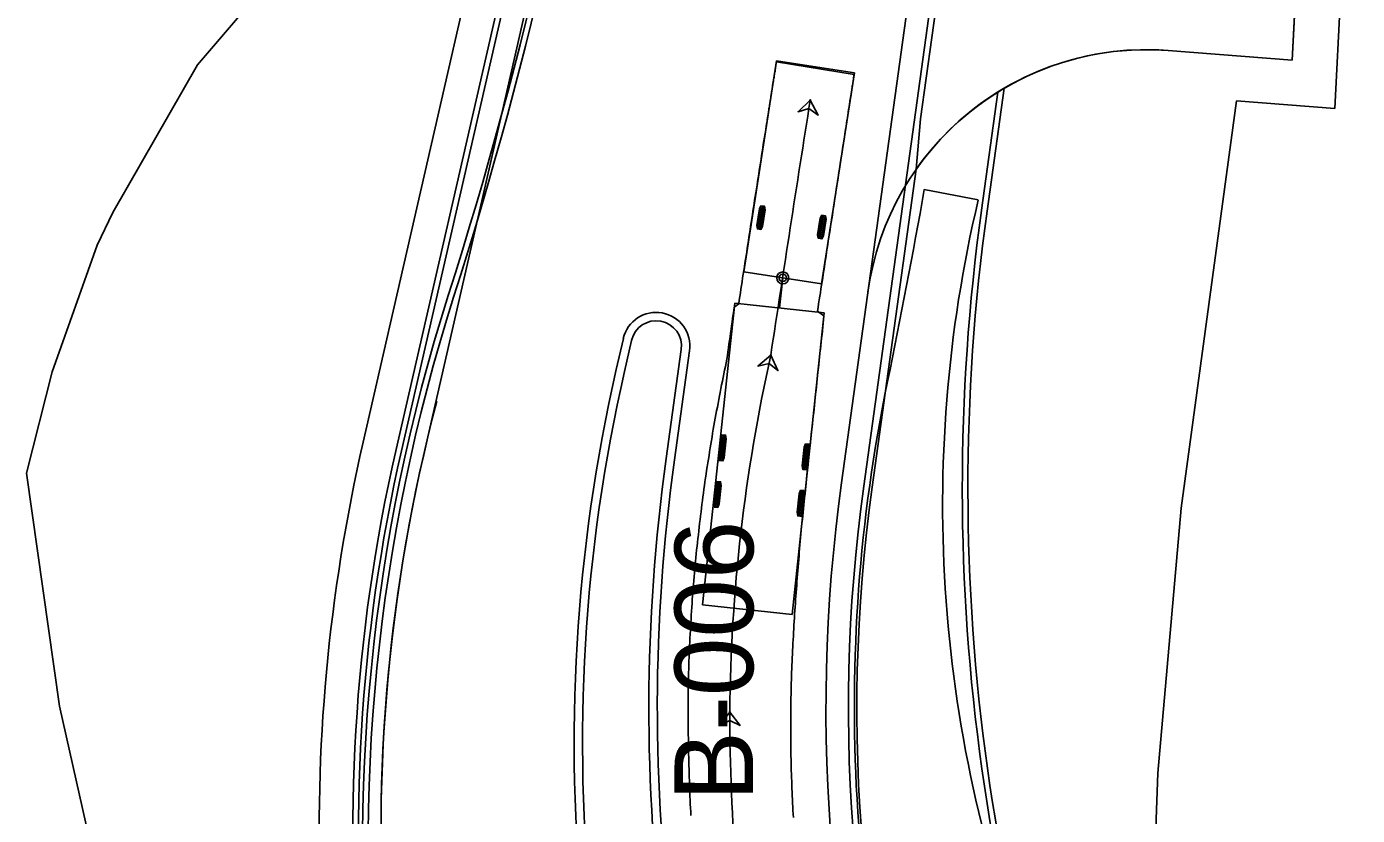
# Model space of a CAD drawing. Extents: x -14 to 1565148, y -25 to 642856.
# Drawn here: x 1564698.7 to 1564817, y 636638 to 636708.2 of the extents above; entities that cross this region are included whole.
import ezdxf

# ---------------------------------------------------------------- set-up
doc = ezdxf.new("R2010")
doc.units = 0
for name, color, linetype in [('DR_P_Drainage_Area', 7, 'Continuous'), ('DR_P_Erosion_Control', 7, 'Continuous'), ('DR_P_Headwall', 7, 'Continuous'), ('GE_X_Alignment', 7, 'Continuous'), ('PV_P_Drive', 7, 'Continuous'), ('PV_P_EOP', 7, 'Continuous'), ('PV_X_COP', 7, 'Continuous'), ('PV_X_EOP', 7, 'Continuous'), ('SC_Scratch10', 7, 'Continuous'), ('SC_Scratch2', 7, 'Continuous'), ('VG_P_Text', 7, 'Continuous')]:
    doc.layers.add(name, color=color, linetype=linetype)

msp = doc.modelspace()

# ---------------------------------------------------------------- linework, layer by layer
at = {"layer": 'DR_P_Drainage_Area'}
for centre, radius, start, end in [((1564357.36, 636804.71), 397.5, 342.3578, 1.7978), ((1564357.36, 636804.71), 398, 342.3578, 1.7978), ((1564891.02, 636634.99), 162.5, 162.3578, 209.8794), ((1564891.02, 636634.99), 162, 162.3578, 209.8794)]:
    msp.add_arc(centre, radius, start, end, dxfattribs=at)
at = {"layer": 'DR_P_Erosion_Control'}
msp.add_arc((1564880.18, 636636.52), 150, 165.1984, 204.9588, dxfattribs=at)
at = {"layer": 'DR_P_Headwall'}
for p, q in [((1564765.37, 636705.12), (1564762.46, 636686.35)), ((1564772.29, 636704.05), (1564765.37, 636705.12)), ((1564765.37, 636705.12), (1564765.37, 636705.12)), ((1564769.38, 636685.28), (1564772.29, 636704.05)), ((1564764.01, 636692.22), (1564763.69, 636690.16)), ((1564764.14, 636692.2), (1564763.82, 636690.14)), ((1564764.27, 636692.18), (1564763.95, 636690.12)), ((1564769.42, 636691.38), (1564769.11, 636689.32)), ((1564769.55, 636691.36), (1564769.23, 636689.3)), ((1564769.68, 636691.34), (1564769.36, 636689.28)), ((1564762.46, 636686.35), (1564769.38, 636685.28)), ((1564765.92, 636685.81), (1564765.64, 636683.13)), ((1564765.92, 636685.81), (1564765.92, 636685.81)), ((1564761.66, 636683.55), (1564758.79, 636656.7)), ((1564769.61, 636682.7), (1564761.66, 636683.55)), ((1564761.66, 636683.55), (1564761.66, 636683.55)), ((1564766.75, 636655.85), (1564769.61, 636682.7)), ((1564760.54, 636671.84), (1564760.29, 636669.55)), ((1564760.67, 636671.82), (1564760.42, 636669.54)), ((1564760.8, 636671.81), (1564760.55, 636669.52)), ((1564767.98, 636671.04), (1564767.73, 636668.76)), ((1564768.11, 636671.03), (1564767.86, 636668.74)), ((1564768.23, 636671.01), (1564767.99, 636668.73)), ((1564760.1, 636667.69), (1564759.85, 636665.41)), ((1564760.23, 636667.68), (1564759.98, 636665.39)), ((1564760.36, 636667.67), (1564760.11, 636665.38)), ((1564767.53, 636666.9), (1564767.29, 636664.61)), ((1564767.66, 636666.89), (1564767.42, 636664.6)), ((1564767.79, 636666.87), (1564767.55, 636664.58)), ((1564758.79, 636656.7), (1564766.75, 636655.85))]:
    msp.add_line(p, q, dxfattribs=at)
for points in [[(1564757.74, 636637.95), (1564757.73, 636638.3), (1564757.71, 636638.64), (1564757.69, 636638.98), (1564757.68, 636639.33), (1564757.66, 636639.67), (1564757.65, 636640.01), (1564757.63, 636640.36), (1564757.62, 636640.7), (1564757.61, 636641.04), (1564757.6, 636641.39), (1564757.59, 636641.73), (1564757.58, 636642.07), (1564757.57, 636642.42), (1564757.56, 636642.76), (1564757.55, 636643.1), (1564757.54, 636643.45), (1564757.53, 636643.79), (1564757.53, 636644.13), (1564757.52, 636644.48), (1564757.52, 636644.82), (1564757.51, 636645.17), (1564757.51, 636645.51), (1564757.5, 636645.85), (1564757.5, 636646.2), (1564757.5, 636646.54), (1564757.5, 636646.88), (1564757.5, 636647.23), (1564757.5, 636647.57), (1564757.5, 636647.92), (1564757.5, 636648.26), (1564757.5, 636648.6), (1564757.5, 636648.95), (1564757.51, 636649.29), (1564757.51, 636649.63), (1564757.52, 636649.98), (1564757.53, 636650.32), (1564757.54, 636650.66), (1564757.55, 636651.01), (1564757.56, 636651.35), (1564757.57, 636651.69), (1564757.58, 636652.04), (1564757.6, 636652.38), (1564757.61, 636652.72), (1564757.63, 636653.06), (1564757.65, 636653.41), (1564757.66, 636653.75), (1564757.68, 636654.09), (1564757.7, 636654.43), (1564757.72, 636654.78), (1564757.74, 636655.12), (1564757.76, 636655.46), (1564757.78, 636655.8), (1564757.8, 636656.14), (1564757.83, 636656.49), (1564757.85, 636656.83), (1564757.87, 636657.17), (1564757.9, 636657.51), (1564757.93, 636657.85), (1564757.95, 636658.19), (1564757.98, 636658.53), (1564758.01, 636658.87), (1564758.04, 636659.21), (1564758.07, 636659.55), (1564758.1, 636659.9), (1564758.13, 636660.24), (1564758.16, 636660.58), (1564758.19, 636660.92), (1564758.23, 636661.25), (1564758.26, 636661.59), (1564758.3, 636661.93), (1564758.33, 636662.27), (1564758.37, 636662.61), (1564758.41, 636662.95), (1564758.45, 636663.29), (1564758.48, 636663.63), (1564758.52, 636663.96), (1564758.56, 636664.3), (1564758.6, 636664.64), (1564758.65, 636664.98), (1564758.69, 636665.31), (1564758.73, 636665.65), (1564758.78, 636665.99), (1564758.82, 636666.32), (1564758.86, 636666.66), (1564758.91, 636666.99), (1564758.96, 636667.33), (1564759, 636667.67), (1564759.05, 636668), (1564759.1, 636668.33), (1564759.15, 636668.67), (1564759.2, 636669), (1564759.25, 636669.34), (1564759.3, 636669.67), (1564759.36, 636670), (1564759.41, 636670.34), (1564759.46, 636670.67), (1564759.52, 636671), (1564759.57, 636671.33), (1564759.63, 636671.66), (1564759.68, 636671.99), (1564759.74, 636672.33), (1564759.8, 636672.66), (1564759.86, 636672.99), (1564759.92, 636673.32), (1564759.98, 636673.65), (1564760.04, 636673.98), (1564760.1, 636674.31), (1564760.16, 636674.64), (1564760.22, 636674.97), (1564760.29, 636675.3), (1564760.35, 636675.62), (1564760.41, 636675.95), (1564760.48, 636676.28), (1564760.55, 636676.61), (1564760.61, 636676.94), (1564760.68, 636677.27), (1564760.75, 636677.59), (1564760.82, 636677.92), (1564760.89, 636678.25), (1564760.94, 636678.58), (1564760.99, 636678.91), (1564761.04, 636679.24), (1564761.08, 636679.57), (1564761.13, 636679.9), (1564761.18, 636680.23), (1564761.23, 636680.56), (1564761.27, 636680.89), (1564761.32, 636681.22), (1564761.37, 636681.55), (1564761.42, 636681.88), (1564761.46, 636682.21), (1564761.51, 636682.55), (1564761.56, 636682.88), (1564761.61, 636683.21), (1564762, 636683.49), (1564762.05, 636683.82), (1564762.1, 636684.15), (1564762.15, 636684.48), (1564762.2, 636684.81), (1564762.25, 636685.14), (1564762.3, 636685.47), (1564762.35, 636685.8), (1564762.4, 636686.13), (1564762.45, 636686.46), (1564762.51, 636686.79), (1564762.56, 636687.12), (1564762.61, 636687.45), (1564762.66, 636687.78), (1564762.71, 636688.11), (1564762.76, 636688.44), (1564762.81, 636688.77), (1564762.86, 636689.1), (1564762.91, 636689.43), (1564762.96, 636689.76), (1564763.01, 636690.09), (1564763.06, 636690.42), (1564763.12, 636690.75), (1564763.17, 636691.08), (1564763.22, 636691.41), (1564763.27, 636691.74), (1564763.32, 636692.07), (1564763.37, 636692.4), (1564763.42, 636692.73), (1564763.47, 636693.06), (1564763.52, 636693.39), (1564763.58, 636693.72), (1564763.63, 636694.05), (1564763.68, 636694.38), (1564763.73, 636694.71), (1564763.78, 636695.04), (1564763.83, 636695.37), (1564763.88, 636695.7), (1564763.94, 636696.03), (1564763.99, 636696.36), (1564764.04, 636696.69), (1564764.09, 636697.02), (1564764.14, 636697.35), (1564764.19, 636697.68), (1564764.25, 636698.01), (1564764.3, 636698.34), (1564764.35, 636698.67), (1564764.4, 636698.99), (1564764.45, 636699.32), (1564764.5, 636699.64), (1564764.52, 636699.75), (1564764.54, 636699.86), (1564764.55, 636699.97), (1564764.57, 636700.08), (1564764.59, 636700.19), (1564764.61, 636700.3), (1564764.62, 636700.41), (1564764.64, 636700.52), (1564764.66, 636700.63), (1564764.67, 636700.74), (1564764.69, 636700.85), (1564764.71, 636700.95), (1564764.73, 636701.06), (1564764.74, 636701.17), (1564764.76, 636701.28), (1564764.78, 636701.39), (1564764.8, 636701.5), (1564764.81, 636701.61), (1564764.83, 636701.72), (1564764.85, 636701.83), (1564764.86, 636701.94), (1564764.88, 636702.05), (1564764.9, 636702.16), (1564764.92, 636702.27), (1564764.93, 636702.38), (1564764.95, 636702.48), (1564764.97, 636702.59), (1564764.98, 636702.7), (1564765, 636702.81), (1564765.02, 636702.92), (1564765.04, 636703.03), (1564765.05, 636703.14), (1564765.07, 636703.25), (1564765.09, 636703.35), (1564765.11, 636703.46), (1564765.12, 636703.57), (1564765.14, 636703.68), (1564765.16, 636703.79), (1564765.17, 636703.9), (1564765.19, 636704), (1564765.21, 636704.11), (1564765.23, 636704.22), (1564765.24, 636704.32), (1564765.26, 636704.43), (1564765.28, 636704.54), (1564765.29, 636704.64), (1564765.31, 636704.75), (1564765.33, 636704.86), (1564765.34, 636704.96), (1564765.36, 636705.05), (1564772.27, 636703.92), (1564772.25, 636703.82), (1564772.23, 636703.71), (1564772.22, 636703.61), (1564772.2, 636703.5), (1564772.18, 636703.39), (1564772.17, 636703.29), (1564772.15, 636703.18), (1564772.14, 636703.07), (1564772.12, 636702.97), (1564772.1, 636702.86), (1564772.09, 636702.75), (1564772.07, 636702.64), (1564772.05, 636702.54), (1564772.04, 636702.43), (1564772.02, 636702.32), (1564772, 636702.21), (1564771.99, 636702.1), (1564771.97, 636702), (1564771.95, 636701.89), (1564771.93, 636701.78), (1564771.92, 636701.67), (1564771.9, 636701.56), (1564771.88, 636701.45), (1564771.87, 636701.34), (1564771.85, 636701.24), (1564771.83, 636701.13), (1564771.82, 636701.02), (1564771.8, 636700.91), (1564771.78, 636700.8), (1564771.77, 636700.69), (1564771.75, 636700.58), (1564771.73, 636700.47), (1564771.72, 636700.36), (1564771.7, 636700.26), (1564771.68, 636700.15), (1564771.67, 636700.04), (1564771.65, 636699.93), (1564771.63, 636699.82), (1564771.61, 636699.71), (1564771.6, 636699.6), (1564771.58, 636699.49), (1564771.56, 636699.38), (1564771.55, 636699.27), (1564771.53, 636699.16), (1564771.51, 636699.05), (1564771.5, 636698.94), (1564771.48, 636698.84), (1564771.46, 636698.73), (1564771.45, 636698.62), (1564771.4, 636698.29), (1564771.35, 636697.97), (1564771.29, 636697.64), (1564771.24, 636697.31), (1564771.19, 636696.99), (1564771.14, 636696.66), (1564771.09, 636696.33), (1564771.04, 636696), (1564770.99, 636695.67), (1564770.94, 636695.34), (1564770.89, 636695.02), (1564770.84, 636694.69), (1564770.79, 636694.36), (1564770.74, 636694.03), (1564770.68, 636693.7), (1564770.63, 636693.37), (1564770.58, 636693.04)], [(1564768.37, 636701.62), (1564767.28, 636700.59), (1564768.25, 636700.88), (1564769.08, 636700.3), (1564768.37, 636701.62)], [(1564770.58, 636693.04), (1564770.53, 636692.72), (1564770.48, 636692.39), (1564770.43, 636692.06), (1564770.38, 636691.73), (1564770.33, 636691.4), (1564770.28, 636691.07), (1564770.23, 636690.74), (1564770.18, 636690.41), (1564770.13, 636690.08), (1564770.07, 636689.76), (1564770.02, 636689.43), (1564769.97, 636689.1), (1564769.92, 636688.77), (1564769.87, 636688.44), (1564769.82, 636688.11), (1564769.77, 636687.78), (1564769.72, 636687.45), (1564769.67, 636687.13), (1564769.62, 636686.8), (1564769.57, 636686.47), (1564769.52, 636686.14), (1564769.47, 636685.81), (1564769.42, 636685.48), (1564769.37, 636685.15), (1564769.32, 636684.82), (1564769.27, 636684.49), (1564769.21, 636684.17), (1564769.16, 636683.84), (1564769.11, 636683.51), (1564769.06, 636683.18), (1564769.01, 636682.85), (1564769.58, 636682.43), (1564769.55, 636682.1), (1564769.51, 636681.77), (1564769.48, 636681.44), (1564769.44, 636681.11), (1564769.41, 636680.78), (1564769.37, 636680.45), (1564769.34, 636680.12), (1564769.3, 636679.79), (1564769.27, 636679.46), (1564769.23, 636679.12), (1564769.2, 636678.79), (1564769.16, 636678.46), (1564769.13, 636678.13), (1564769.09, 636677.8), (1564769.05, 636677.47), (1564769.02, 636677.14), (1564768.98, 636676.81), (1564768.95, 636676.48), (1564768.91, 636676.15), (1564768.88, 636675.81), (1564768.84, 636675.48), (1564768.81, 636675.15), (1564768.77, 636674.82), (1564768.74, 636674.49), (1564768.7, 636674.16), (1564768.67, 636673.83), (1564768.63, 636673.5), (1564768.6, 636673.17), (1564768.56, 636672.84), (1564768.53, 636672.51), (1564768.49, 636672.18), (1564768.45, 636671.85), (1564768.42, 636671.52), (1564768.38, 636671.19), (1564768.35, 636670.86), (1564768.31, 636670.53), (1564768.28, 636670.21), (1564768.24, 636669.88), (1564768.21, 636669.55), (1564768.17, 636669.22), (1564768.14, 636668.89), (1564768.1, 636668.56), (1564768.07, 636668.24), (1564768.03, 636667.91), (1564768, 636667.58), (1564767.96, 636667.25), (1564767.93, 636666.93), (1564767.9, 636666.6), (1564767.86, 636666.27), (1564767.83, 636665.94), (1564767.79, 636665.62), (1564767.76, 636665.29), (1564767.73, 636664.97), (1564767.7, 636664.64), (1564767.67, 636664.31), (1564767.63, 636663.99), (1564767.6, 636663.66), (1564767.57, 636663.34), (1564767.54, 636663.01), (1564767.51, 636662.69), (1564767.48, 636662.36), (1564767.45, 636662.04), (1564767.42, 636661.71), (1564767.39, 636661.39), (1564767.37, 636661.06), (1564767.34, 636660.74), (1564767.31, 636660.41), (1564767.28, 636660.09), (1564767.26, 636659.76), (1564767.23, 636659.44), (1564767.21, 636659.11), (1564767.18, 636658.79), (1564767.16, 636658.47), (1564767.13, 636658.14), (1564767.11, 636657.82), (1564767.08, 636657.49), (1564767.06, 636657.17), (1564767.04, 636656.84), (1564767.02, 636656.52), (1564766.99, 636656.2), (1564766.97, 636655.87), (1564766.95, 636655.55), (1564766.93, 636655.23), (1564766.91, 636654.9), (1564766.89, 636654.58), (1564766.88, 636654.25), (1564766.86, 636653.93), (1564766.84, 636653.61), (1564766.82, 636653.28), (1564766.81, 636652.96), (1564766.79, 636652.64), (1564766.78, 636652.31), (1564766.76, 636651.99), (1564766.75, 636651.67), (1564766.74, 636651.34), (1564766.72, 636651.02), (1564766.71, 636650.7), (1564766.7, 636650.37), (1564766.69, 636650.05), (1564766.68, 636649.73), (1564766.67, 636649.4), (1564766.66, 636649.08), (1564766.66, 636648.76), (1564766.65, 636648.43), (1564766.64, 636648.11), (1564766.64, 636647.79), (1564766.63, 636647.46), (1564766.63, 636647.14), (1564766.63, 636646.82), (1564766.63, 636646.49), (1564766.63, 636646.17), (1564766.63, 636645.85), (1564766.63, 636645.52), (1564766.63, 636645.2), (1564766.63, 636644.88), (1564766.63, 636644.55), (1564766.64, 636644.23), (1564766.64, 636643.91), (1564766.65, 636643.58), (1564766.65, 636643.26), (1564766.66, 636642.94), (1564766.67, 636642.62), (1564766.68, 636642.29), (1564766.68, 636641.97), (1564766.69, 636641.65), (1564766.71, 636641.32), (1564766.72, 636641), (1564766.73, 636640.68), (1564766.74, 636640.35), (1564766.75, 636640.03), (1564766.77, 636639.71), (1564766.78, 636639.39), (1564766.8, 636639.06), (1564766.82, 636638.74), (1564766.83, 636638.42), (1564766.85, 636638.09), (1564766.87, 636637.77)], [(1564764.86, 636678.92), (1564763.71, 636677.96), (1564764.7, 636678.19), (1564765.49, 636677.56), (1564764.86, 636678.92)], [(1564761.2, 636647.16), (1564760.29, 636645.97), (1564761.2, 636646.41), (1564762.12, 636645.97), (1564761.2, 636647.16)]]:
    msp.add_lwpolyline(points, dxfattribs=at)
for points in [[(1564768.37, 636701.62), (1564767.28, 636700.59), (1564768.25, 636700.88), (1564769.08, 636700.3)], [(1564763.98, 636692.23), (1564764.3, 636692.18), (1564764.35, 636691.87), (1564764.12, 636690.39), (1564763.98, 636690.12), (1564763.66, 636690.17), (1564763.61, 636690.47), (1564763.84, 636691.95)], [(1564769.39, 636691.39), (1564769.71, 636691.34), (1564769.77, 636691.03), (1564769.54, 636689.55), (1564769.4, 636689.28), (1564769.07, 636689.33), (1564769.02, 636689.63), (1564769.25, 636691.11)], [(1564764.86, 636678.92), (1564763.71, 636677.96), (1564764.7, 636678.19), (1564765.49, 636677.56)], [(1564760.51, 636671.84), (1564760.83, 636671.81), (1564760.89, 636671.47), (1564760.72, 636669.83), (1564760.59, 636669.52), (1564760.26, 636669.55), (1564760.2, 636669.88), (1564760.38, 636671.53)], [(1564767.94, 636671.05), (1564768.27, 636671.01), (1564768.33, 636670.68), (1564768.15, 636669.03), (1564768.02, 636668.72), (1564767.7, 636668.76), (1564767.64, 636669.09), (1564767.81, 636670.74)], [(1564760.06, 636667.7), (1564760.39, 636667.66), (1564760.45, 636667.33), (1564760.27, 636665.69), (1564760.14, 636665.38), (1564759.82, 636665.41), (1564759.76, 636665.74), (1564759.93, 636667.39)], [(1564767.5, 636666.9), (1564767.82, 636666.87), (1564767.89, 636666.54), (1564767.71, 636664.89), (1564767.58, 636664.58), (1564767.26, 636664.62), (1564767.19, 636664.95), (1564767.37, 636666.59)], [(1564761.2, 636647.16), (1564760.29, 636645.97), (1564761.2, 636646.41), (1564762.12, 636645.97)]]:
    msp.add_lwpolyline(points, close=True, dxfattribs=at)
for centre, radius in [((1564768.37, 636701.62), 0.0417), ((1564765.92, 636685.81), 0.533), ((1564765.92, 636685.81), 0.333), ((1564764.86, 636678.92), 0.0417), ((1564764.86, 636678.92), 0.0417), ((1564761.2, 636647.16), 0.0417), ((1564761.2, 636647.16), 0.0417)]:
    msp.add_circle(centre, radius, dxfattribs=at)
for centre, radius, start, end in [((1568113.98, 636172.7), 3387.17, 171.01623, 171.40482), ((1564912.43, 636645.83), 151.23, 167.3602, 179.4939), ((1564939.79, 636647.42), 178.59, 180.0842, 189.2876)]:
    msp.add_arc(centre, radius, start, end, dxfattribs=at)
at = {"layer": 'GE_X_Alignment'}
for p, q in [((1564785.05, 636702.35), (1564783.59, 636691.82)), ((1564773.87, 636667.18), (1564777.79, 636695.47)), ((1564751.84, 636677.49), (1564752.47, 636680.24)), ((1564756.89, 636679.43), (1564755.54, 636669.72))]:
    msp.add_line(p, q, dxfattribs=at)
msp.add_lwpolyline([(1564800.19, 636706.05), (1564811.23, 636705.19), (1564812.86, 636736.84), (1564811.23, 636705.19), (1564800.19, 636706.05)], dxfattribs=at)
for centre, radius, start, end in [((1564798.26, 636681.12), 25, 85.5769, 144.5514), ((1564798.26, 636681.12), 25, 85.5769, 144.5514), ((1564798.26, 636681.12), 25, 121.8954, 144.9769), ((1564961.89, 636667.09), 180, 172.1036, 203.8547), ((1564754.66, 636679.74), 2.25, 352.1036, 167.1178), ((1564896.36, 636644.43), 148.25, 167.1178, 204.9588), ((1564915.76, 636647.5), 161.75, 172.1036, 202.9822), ((1564915.76, 636647.5), 143.25, 172.1036, 198.1955)]:
    msp.add_arc(centre, radius, start, end, dxfattribs=at)
at = {"layer": 'PV_P_Drive'}
msp.add_line((1564783.31, 636692.74), (1564778.51, 636693.67), dxfattribs=at)
for centre, radius, start, end in [((1564171.43, 636801.02), 616.5, 348.35565, 349.97217), ((1564898.14, 636665.59), 118, 166.6995, 201.6161), ((1564915.79, 636647.63), 143.5, 168.3556, 198.1955)]:
    msp.add_arc(centre, radius, start, end, dxfattribs=at)
at = {"layer": 'PV_P_EOP'}
for p, q in [((1564773.12, 636667.28), (1564780.67, 636721.69)), ((1564778.16, 636699.96), (1564781.17, 636721.62)), ((1564731.52, 636670.52), (1564742.67, 636719.26)), ((1564732.01, 636670.41), (1564743.16, 636719.15)), ((1564785.05, 636702.35), (1564783.59, 636691.82)), ((1564785.61, 636702.68), (1564784.09, 636691.75)), ((1564777.79, 636695.47), (1564778.16, 636699.96)), ((1564773.87, 636667.18), (1564777.79, 636695.47)), ((1564751.11, 636677.65), (1564751.74, 636680.41)), ((1564751.84, 636677.49), (1564752.47, 636680.24)), ((1564755.54, 636669.72), (1564756.89, 636679.43)), ((1564756.29, 636669.62), (1564757.63, 636679.32))]:
    msp.add_line(p, q, dxfattribs=at)
for centre, radius, start, end in [((1564961.89, 636667.09), 180, 172.1036, 203.8547), ((1564961.89, 636667.09), 179.5, 172.1036, 203.8547), ((1564754.66, 636679.74), 3, 352.1036, 167.1178), ((1564754.66, 636679.74), 2.25, 352.1036, 167.1178), ((1564896.36, 636644.43), 149, 167.1178, 204.9588), ((1564896.36, 636644.43), 148.25, 167.1178, 204.9588), ((1564880.18, 636636.52), 152.5, 167.1178, 204.9588), ((1564880.18, 636636.52), 152, 167.1178, 204.9588), ((1564915.76, 636647.5), 161.75, 172.1036, 202.9822), ((1564915.76, 636647.5), 161, 172.1036, 202.9822), ((1564915.76, 636647.5), 144, 172.1036, 198.1955), ((1564915.76, 636647.5), 143.25, 172.1036, 198.1955)]:
    msp.add_arc(centre, radius, start, end, dxfattribs=at)
at = {"layer": 'PV_X_COP'}
for q in [(1564812.86, 636736.84), (1564800.19, 636706.05)]:
    msp.add_line((1564811.23, 636705.19), q, dxfattribs=at)
msp.add_arc((1564798.26, 636681.12), 25, 85.5769, 172.1036, dxfattribs=at)
at = {"layer": 'PV_X_EOP'}
for p, q in [((1564771.14, 636667.56), (1564778.69, 636721.97)), ((1564733.96, 636669.96), (1564745.11, 636718.7))]:
    msp.add_line(p, q, dxfattribs=at)
for centre, radius, start, end in [((1564880.18, 636636.52), 150, 167.1178, 204.9588), ((1564915.76, 636647.5), 146, 172.1036, 198.1955)]:
    msp.add_arc(centre, radius, start, end, dxfattribs=at)
at = {"layer": 'SC_Scratch10'}
msp.add_line((1564728.6, 636671.19), (1564739.75, 636719.93), dxfattribs=at)
msp.add_arc((1564880.18, 636636.52), 155.5, 167.1178, 197.6442, dxfattribs=at)
at = {"layer": 'SC_Scratch2'}
for q in [(1564817.03, 636740.06), (1564806.27, 636701.56)]:
    msp.add_line((1564815.02, 636700.89), q, dxfattribs=at)
for points in [[(1564704.93, 636688.71), (1564706.33, 636691.63), (1564713.87, 636704.78), (1564725.03, 636717.86), (1564734.35, 636738.84), (1564736.25, 636743.65), (1564738.19, 636757.02), (1564740.07, 636769.72), (1564714.31, 636805.46)], [(1564806.27, 636701.56), (1564801.35, 636665.3), (1564799.29, 636641.73), (1564798.7, 636625.3), (1564797.01, 636610.72), (1564798.9, 636602.6)], [(1564698.66, 636668.43), (1564700.93, 636677.45), (1564704.93, 636688.71)], [(1564698.66, 636668.43), (1564701.57, 636647.7), (1564708.63, 636616.26)]]:
    msp.add_lwpolyline(points, dxfattribs=at)

# ---------------------------------------------------------------- texts
at = {"layer": 'VG_P_Text'}
msp.add_text('B-006', height=7, rotation=89.94, dxfattribs=at).set_placement((1564763.28, 636639.22))

doc.saveas('drawing.dxf')
